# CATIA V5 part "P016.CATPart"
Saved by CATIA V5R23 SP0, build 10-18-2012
Part number: P016
Definition: Rlt rigide d30 D62 b16
Description: Rlt rigide 6206 d30 D62 b16
Bounding box of the stored display mesh (mm): x -8 to 8, y -30.959 to 30.959, z -30.959 to 30.959
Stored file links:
  C:\wamp\www\COURS\CONCEPTION GMP1\TITRE 02-SEMESTRE 2\03-TP7-PRESSE MECANIQUE\eleve\P016.CATPart
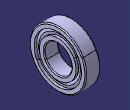
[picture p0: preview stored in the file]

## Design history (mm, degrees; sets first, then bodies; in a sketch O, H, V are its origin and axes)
Parameters
  PartNumber = "Rlt rigide 6206 d30 D62 b16"
  Designation = "Rlt_rigide_61804_d20_D32_b7"
  diametre_interieur = 30 mm
  diametre_exterieur = 62 mm
  largeur = 16 mm
  rayon = 1 mm
  diametre_bille = 12 mm
  diam_eplt_int = 40.3 mm
  diam_eplt_ext = 52.1 mm
  c_dynam = 19500 (force)
  co = 10000 (force)
Body1 (main body)
  Sketch1 on xy-plane, origin (0, 0, 0), H (1, 0, 0), V (0, 1, 0)
    axis line L1 (-8, 0) -> (8, 0)
    point P1 (-8, 0)
    point P2 (8, 0)
    arc A1 centre (0, 23) radius 6 from (-5.2799, 20.15) to (5.2799, 20.15) ccw
    point P3 (0, 23)
    line L2 (-8, 20.15) -> (-5.2799, 20.15)
    line L3 (8, 20.15) -> (8, 16)
    line L4 (7, 15) -> (-7, 15)
    line L5 (-8, 16) -> (-8, 20.15)
    point P6 (5.2799, 20.15)
    line L6 (5.2799, 20.15) -> (8, 20.15)
    arc A2 centre (7, 16) radius 1 from (8, 16) to (7, 15) cw
    arc A3 centre (-7, 16) radius 1 from (-7, 15) to (-8, 16) cw
    radius A2 = 1 {= rayon}
    radius A3 = 1 {= rayon}
    radius A1 = 6 {= diametre_bille /2}
    distance L4 L1 = 15 {= diametre_interieur /2}
    distance L5 L3 = 16 {= largeur}
    distance P3 L1 = 23 {= (diametre_exterieur+diametre_interieur )/4}
    distance L6 L1 = 20.15 {= diam_eplt_int /2}
    coincidence: P1 H, P3 V, L2 P6, L2 L6, P1 L5, P2 L3
    horizontal: L1 H, L2 H, L4 H, L6 H
    vertical: L3 V, L5 V
    symmetry: L3 L5 V
    tangency: A2 L3, A2 L4, A3 L4, A3 L5
  Shaft1: profile Sketch1, axis Sketch1.L1, angle 360
Body2
  Sketch2 on xy-plane, origin (0, 0, 0), H (1, 0, 0), V (0, 1, 0)
    circle A1 centre (0, 23) radius 6
    point P1 (0, 23)
    reference projected arc E1 centre (0, 23) radius 6 from (-5.2799, 20.15) to (5.2799, 20.15) ccw from element of Sketch1
    axis line L1 (-6, 0) -> (6, 0)
    point P2 (-6, 0)
    point P3 (6, 0)
    length L1 = 12 {= diametre_bille}
    coincidence: P1 V, A1 E1, P2 H
    horizontal: L1 H
    symmetry: P2 P3 V
  Shaft2: profile Sketch2, axis Sketch2.L1, angle 360
Body3
  Sketch3 on xy-plane, origin (0, 0, 0), H (1, 0, 0), V (0, 1, 0)
    line L1 (-7, 31) -> (7, 31)
    line L2 (8, 30) -> (8, 26.05)
    line L3 (8, 26.05) -> (5.167, 26.05)
    line L4 (-8, 26.05) -> (-8, 30)
    reference projected line E1 (-8, 20.15) -> (-8, 16) from element of Sketch1
    reference projected line E2 (8, 16) -> (8, 20.15) from element of Sketch1
    arc A1 centre (0, 23) radius 6 from (5.167, 26.05) to (-5.167, 26.05) ccw
    point P3 (0, 23)
    reference projected arc E3 centre (0, 23) radius 6 from (-5.2799, 20.15) to (5.2799, 20.15) ccw from element of Sketch1
    arc A2 centre (-7, 30) radius 1 from (-7, 31) to (-8, 30) ccw
    arc A3 centre (7, 30) radius 1 from (8, 30) to (7, 31) ccw
    axis line L5 (-8, 0) -> (8, 0)
    point P10 (-8, 0)
    point P11 (8, 0)
    line L6 (-5.167, 26.05) -> (-8, 26.05)
    radius A2 = 1 {= rayon}
    radius A3 = 1 {= rayon}
    distance L5 L1 = 31 {= diametre_exterieur /2}
    distance L3 P11 = 26.05 {= diam_eplt_ext /2}
    horizontal: L1 H, L3 H, L6 H
    vertical: L2 V, L4 V
    coincidence: E1 L4, L2 E2, P3 V, E3 A1, P10 L4, P11 L2, H L5, L3 L6
    tangency: A2 L1, A2 L4, A3 L2, A3 L1
  Shaft3: profile Sketch3, axis Sketch3.L5, angle 360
